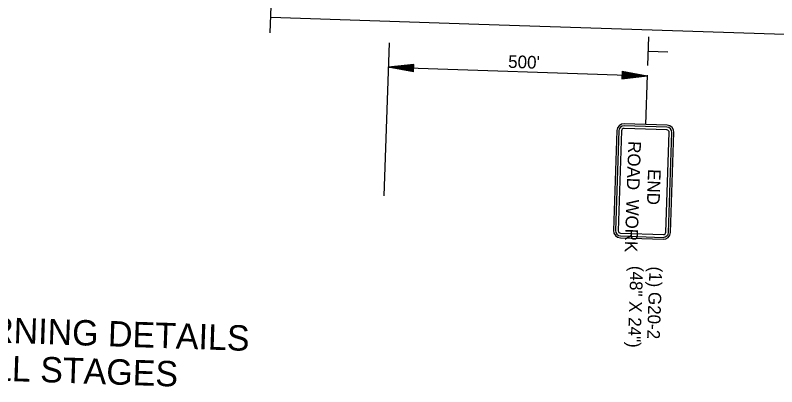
# Model space of a CAD drawing. Extents: x 977269 to 979191, y 1525946 to 1526973.
# Drawn here: x 978075.3 to 978434.9, y 1526430.7 to 1526606.5 of the extents above; entities that cross this region are included whole.
import ezdxf

# ---------------------------------------------------------------- set-up
doc = ezdxf.new("R2010")
doc.units = 0
for name, color, linetype in [('R_Border', 7, 'Continuous'), ('STAMP', 7, 'Continuous'), ('STAMP_PP', 7, 'Continuous')]:
    doc.layers.add(name, color=color, linetype=linetype)

msp = doc.modelspace()

# ---------------------------------------------------------------- linework, layer by layer
at = {"layer": 'STAMP'}
for p, q in [((978195.71, 1526598.17), (978196.86, 1526632.6)), ((978294.14, 1526602.09), (978195.95, 1526605.36)), ((978727.91, 1526587.62), (978294.14, 1526602.09)), ((978374.34, 1526596.17), (978373.89, 1526582.72)), ((978251.82, 1526593.34), (978249.41, 1526521.07)), ((978374.31, 1526589.47), (978383.5, 1526589.16)), ((978263.45, 1526583.2), (978251.43, 1526581.81)), ((978251.43, 1526581.81), (978373.74, 1526577.73)), ((978263.33, 1526579.61), (978251.43, 1526581.81)), ((978263.44, 1526582.9), (978253.43, 1526581.74)), ((978263.34, 1526579.91), (978253.43, 1526581.74)), ((978263.43, 1526582.6), (978255.49, 1526581.67)), ((978263.35, 1526580.22), (978255.49, 1526581.67)), ((978263.42, 1526582.3), (978257.48, 1526581.61)), ((978263.36, 1526580.52), (978257.48, 1526581.61)), ((978263.41, 1526581.99), (978259.51, 1526581.54)), ((978263.38, 1526580.83), (978259.51, 1526581.54)), ((978263.4, 1526581.69), (978261.51, 1526581.47)), ((978263.39, 1526581.13), (978261.51, 1526581.47)), ((978263.33, 1526579.61), (978263.45, 1526583.2)), ((978361.83, 1526579.92), (978361.71, 1526576.33)), ((978361.83, 1526579.92), (978373.74, 1526577.73)), ((978361.71, 1526576.33), (978373.74, 1526577.73)), ((978361.72, 1526576.63), (978371.74, 1526577.8)), ((978361.73, 1526576.94), (978369.68, 1526577.86)), ((978361.74, 1526577.24), (978367.69, 1526577.93)), ((978361.75, 1526577.54), (978365.66, 1526578)), ((978361.76, 1526577.85), (978363.66, 1526578.07)), ((978361.78, 1526578.41), (978363.66, 1526578.07)), ((978361.79, 1526578.71), (978365.66, 1526578)), ((978361.8, 1526579.02), (978367.69, 1526577.93)), ((978361.81, 1526579.32), (978369.68, 1526577.86)), ((978361.82, 1526579.62), (978371.74, 1526577.8)), ((978373.74, 1526578.06), (978372.96, 1526554.78))]:
    msp.add_line(p, q, dxfattribs=at)
at = {"layer": 'STAMP_PP'}
for p, q in [((978383.08, 1526554.44), (978362.84, 1526555.12)), ((978359.36, 1526551.86), (978357.78, 1526504.63)), ((978360.29, 1526551.83), (978358.72, 1526504.6)), ((978361.61, 1526551.78), (978360.03, 1526504.56)), ((978383.01, 1526552.2), (978362.77, 1526552.87)), ((978383.05, 1526553.51), (978362.81, 1526554.18)), ((978382.52, 1526503.81), (978384.09, 1526551.03)), ((978383.83, 1526503.77), (978385.4, 1526550.99)), ((978384.77, 1526503.73), (978386.34, 1526550.96)), ((978361.04, 1526501.15), (978381.28, 1526500.47)), ((978361.07, 1526502.09), (978381.31, 1526501.41)), ((978361.12, 1526503.4), (978381.36, 1526502.72))]:
    msp.add_line(p, q, dxfattribs=at)
for centre, radius, start, end in [((978362.73, 1526551.75), 3.37, 88.0901, 178.0901), ((978362.73, 1526551.75), 2.44, 88.0901, 178.0901), ((978362.73, 1526551.75), 1.13, 88.0901, 178.0901), ((978382.97, 1526551.07), 1.13, 358.0901, 88.0901), ((978382.97, 1526551.07), 2.44, 358.0901, 88.0901), ((978382.97, 1526551.07), 3.38, 358.0901, 88.0901), ((978361.16, 1526504.52), 3.37, 178.0901, 268.0901), ((978361.16, 1526504.52), 2.44, 178.0901, 268.0901), ((978361.16, 1526504.52), 1.13, 178.0901, 268.0901), ((978381.39, 1526503.85), 3.37, 268.0901, 358.0901), ((978381.39, 1526503.85), 2.44, 268.0901, 358.0901), ((978381.39, 1526503.85), 1.13, 268.0901, 358.0901)]:
    msp.add_arc(centre, radius, start, end, dxfattribs=at)

# ---------------------------------------------------------------- texts
at = {"layer": 'R_Border'}
for s, height, rotation, p in [('(48" X 24")', 6, 268.0901, (978365.82, 1526487.99)), ('(1) G20-2', 6, 268.0901, (978374.82, 1526487.69)), ('ADVANCE WARNING DETAILS', 12, 358.0901, (977954.93, 1526455.38)), ('ALL SITES - ALL STAGES', 12, 358.0901, (977960.33, 1526437.19))]:
    msp.add_text(s, height=height, rotation=rotation, dxfattribs=at).set_placement(p)
at = {"layer": 'STAMP'}
msp.add_text("500'", height=6, rotation=358.0901, dxfattribs=at).set_placement((978307.97, 1526581.58))
at = {"layer": 'STAMP_PP'}
for s, p in [('ROAD  WORK', (978364.82, 1526547.01)), ('END', (978374.14, 1526533.76))]:
    msp.add_text(s, height=6, rotation=268.0901, dxfattribs=at).set_placement(p)

doc.saveas('drawing.dxf')
